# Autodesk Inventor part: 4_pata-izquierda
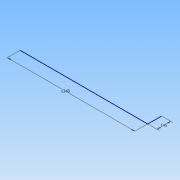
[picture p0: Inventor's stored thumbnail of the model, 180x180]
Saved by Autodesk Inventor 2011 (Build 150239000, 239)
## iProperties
Created: 2020-12
Part Number: 4_pata-izquierda
Document SubType Name: Modeling
Designer: PC
Density: 1 g/cm^3
Author: PC
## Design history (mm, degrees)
sketch "Sketch1"
  geometry: L1 (0, 0)-(1340, 0); L2 (1340, 0)-(1340, 145)
  constraints: 4 end point, 1 horizontal, 1 perpendicular
  dimensions: "d0" = 1340 dimension on L1.start L1.end L1 L2.end L2; "d0" = 1340 distance of L1.start L1.end; "d1" = 145 distance of L1.end L2.end
